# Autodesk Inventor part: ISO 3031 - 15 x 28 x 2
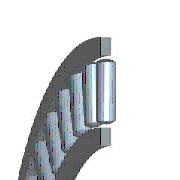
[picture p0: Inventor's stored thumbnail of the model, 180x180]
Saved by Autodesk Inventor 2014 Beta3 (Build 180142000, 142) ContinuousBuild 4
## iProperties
Created: 2012-11
Part Number: ISO 3031 - 15 x 28 x 2
Material: Steel, Mild
Description: Rolling bearings - thrust needle roller and cage assemblies, thrust washers - boundary dimensions and tolerances
Document SubType Name: Modeling
Standard: ISO 3031
Designer: Thomas
Standard Revision: Third edition 2000-08-01
Standards Organization: ISO
Language: en-US
Size Designation: 15 x 28 x 2
Categories: <MemberInstance><Categories><Category DisplayName="Shaft Parts" InternalName="7f7aeb1f-a693-4053-b835-cee3144e0d98" Mnemonic="SHFT"><Category DisplayName="Beari
Density: 1 g/cm^3
Appearance: Steel
IsCustomPart: 0
Author: Thomas
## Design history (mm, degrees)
revolve "Body" stored, may be unused: angle "d36" = 90 deg
sketch "Sketch"
  geometry: L1 (-7.5, 0.6)-(-14, 0.6); L2 (-14, -0.6)-(-14, 0.6); L3 (-7.5, -0.6)-(-14, -0.6); L4 (-7.5, 0.6)-(-7.5, -0.6); L5 (-8.605, 1.2)-(-8.605, -1.2); L6 (-12.895, 1.2)-(-12.895, -1.2); L7 (-12.505, 1)-(-8.995, 1); L8 (-12.895, 1.2)-(-8.605, 1.2); L9 (-12.895, -1.2)-(-8.605, -1.2); L10 (-13.5, 0)-(0.5, 0) reference; L11 (0, -2.52)-(0, 2.52) reference; L12 (-10.75, 1)-(-10.75, -1.5); A1 r 2 centre (-10.773, 0) between (-12.505, 1) and (-12.773, 0); A2 r 2 centre (-10.727, 0) between (-8.727, 0) and (-8.995, 1)
  constraints: 20 end point, 4 point on circle, 4 point on line, 2 centre point, 2 parallel, 1 equal radius, 1 midpoint, 1 symmetric about line, 3 other
  dimensions: "d0" = 2 radius of A2 (= KB); "d2" = 15 diameter of L4 L11 (= WD); "d3" = 28 diameter of L2 L11 (= BD); "d4" = 17.99 diameter of L7.end L11 (= 0.77 x WD + 0.23 x BD); "d5" = 17.21 diameter of L5 L11 (= 0.83 x WD + 0.17 x BD); "d6" = 25.79 diameter of L6 L11 (= 0.83 x BD + 0.17 x WD); "d7" = 21.5 diameter of L12.end L11 (= 0.5 x WD + 0.5 x BD); "d8" = 2 diameter of L7 L10 (= KB); "d9" = 2.4 diameter of L8 L10 (= 1.2 x KB); "d10" = 1.2 diameter of L3 L10 (= 0.6 x KB)
extrude "Groove" cut sketch "Sketch" stored distance "d11" = 2.4 (= 1.2 x KB); taper "d12" = 0 deg
revolve "Roller" stored, may be unused: angle "d64" = 90 deg
pattern_circular "Grooves" dims angle "d14" = 360 deg
node "IDS_WORKPLANE{1}"
node "IDS_WORKPLANE{2}"
body "Solid1"
other parameters: "WD" = 15 [user parameter; used in 7 equation terms], "BD" = 28 [user parameter; used in 6 equation terms], "KB" = 2 [user parameter; used in 8 equation terms], "d1" = 0, "d68" = 0.4 (= 0.2 x KB), "d69" = 0.4 (= 0.2 x KB), "d70" = 0, "d71" = 0, "BBA" = 90 deg [user parameter], "BC0" = 3.75e+07 [user parameter], "BC" = 1.04e+07 [user parameter], "BR" = 14 (= 0.5 x BD) [user parameter], "WR" = 7.5 (= 0.5 x WD) [user parameter]
